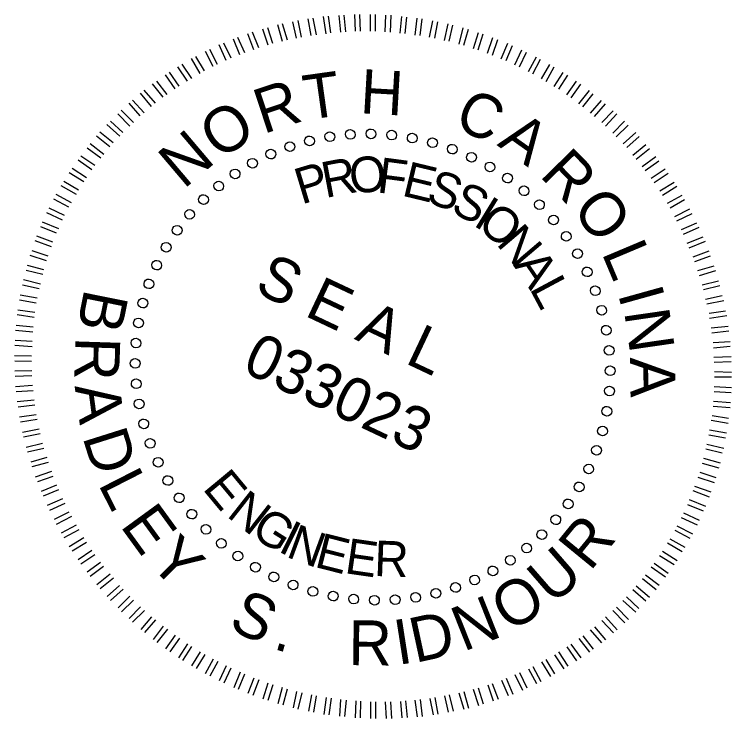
# Model space of a CAD drawing. Extents: x 1519210 to 1521378, y 637447 to 639183.
# Drawn here: x 1521293.4 to 1521377.9, y 638204.2 to 638287.1 of the extents above; entities that cross this region are included whole.
import ezdxf

# ---------------------------------------------------------------- set-up
doc = ezdxf.new("R2010")
doc.units = 0
doc.layers.add('Old_Level_2', color=7, linetype='Continuous')

msp = doc.modelspace()

# ---------------------------------------------------------------- linework, layer by layer
at = {"layer": 'Old_Level_2'}
for p, q in [((1521332.409, 638285.033), (1521332.203, 638287.004)), ((1521333.571, 638285.091), (1521333.479, 638287.063)), ((1521334.142, 638285.098), (1521334.05, 638287.069)), ((1521335.329, 638285.088), (1521335.305, 638287.083)), ((1521335.9, 638285.095), (1521335.922, 638287.067)), ((1521337.066, 638285.04), (1521337.135, 638286.991)), ((1521326.612, 638284.296), (1521326.157, 638286.219)), ((1521327.179, 638284.415), (1521326.791, 638286.361)), ((1521328.338, 638284.585), (1521327.971, 638286.575)), ((1521328.951, 638284.681), (1521328.563, 638286.627)), ((1521330.088, 638284.806), (1521329.789, 638286.82)), ((1521330.655, 638284.924), (1521330.381, 638286.871)), ((1521331.817, 638284.982), (1521331.611, 638286.952)), ((1521337.662, 638284.98), (1521337.752, 638286.976)), ((1521338.807, 638284.88), (1521338.99, 638286.833)), ((1521339.403, 638284.82), (1521339.586, 638286.772)), ((1521340.573, 638284.654), (1521340.824, 638286.629)), ((1521341.169, 638284.593), (1521341.419, 638286.568)), ((1521342.271, 638284.403), (1521342.661, 638286.313)), ((1521342.892, 638284.276), (1521343.236, 638286.207)), ((1521323.263, 638283.452), (1521322.626, 638285.35)), ((1521323.804, 638283.638), (1521323.213, 638285.514)), ((1521324.938, 638283.874), (1521324.389, 638285.841)), ((1521325.526, 638284.038), (1521324.956, 638285.959)), ((1521344.02, 638284.019), (1521344.478, 638285.952)), ((1521344.595, 638283.914), (1521345.031, 638285.801)), ((1521345.748, 638283.59), (1521346.251, 638285.501)), ((1521346.301, 638283.44), (1521346.851, 638285.329)), ((1521321.592, 638282.918), (1521320.887, 638284.793)), ((1521322.155, 638283.149), (1521321.429, 638284.978)), ((1521347.432, 638283.071), (1521348.029, 638284.938)), ((1521347.986, 638282.92), (1521348.582, 638284.788)), ((1521318.91, 638281.925), (1521318.048, 638283.708)), ((1521319.946, 638282.317), (1521319.174, 638284.169)), ((1521320.509, 638282.547), (1521319.715, 638284.354)), ((1521349.096, 638282.507), (1521349.739, 638284.352)), ((1521349.675, 638282.289), (1521350.318, 638284.134)), ((1521350.717, 638281.853), (1521351.475, 638283.699)), ((1521317.314, 638281.189), (1521316.385, 638282.95)), ((1521318.326, 638281.649), (1521317.485, 638283.478)), ((1521351.296, 638281.635), (1521352.032, 638283.436)), ((1521352.317, 638281.153), (1521353.146, 638282.911)), ((1521315.766, 638280.433), (1521314.747, 638282.125)), ((1521316.798, 638280.937), (1521315.869, 638282.698)), ((1521352.874, 638280.89), (1521353.703, 638282.648)), ((1521353.921, 638280.342), (1521354.864, 638282.1)), ((1521314.267, 638279.542), (1521313.135, 638281.233)), ((1521315.274, 638280.113), (1521314.231, 638281.872)), ((1521354.432, 638280.101), (1521355.354, 638281.814)), ((1521355.457, 638279.507), (1521356.425, 638281.199)), ((1521312.768, 638278.651), (1521311.661, 638280.275)), ((1521313.776, 638279.222), (1521312.644, 638280.913)), ((1521355.993, 638279.199), (1521356.961, 638280.891)), ((1521356.951, 638278.582), (1521358.012, 638280.23)), ((1521312.324, 638278.31), (1521311.17, 638279.956)), ((1521357.487, 638278.274), (1521358.548, 638279.922)), ((1521310.897, 638277.33), (1521309.654, 638278.908)), ((1521311.388, 638277.649), (1521310.145, 638279.227)), ((1521358.423, 638277.612), (1521359.577, 638279.217)), ((1521358.938, 638277.259), (1521360.092, 638278.864)), ((1521309.542, 638276.261), (1521308.231, 638277.816)), ((1521310.007, 638276.648), (1521308.676, 638278.157)), ((1521359.853, 638276.552), (1521361.1, 638278.113)), ((1521360.321, 638276.221), (1521361.547, 638277.737)), ((1521308.677, 638275.512), (1521307.278, 638276.998)), ((1521361.215, 638275.469), (1521362.534, 638276.941)), ((1521308.211, 638275.126), (1521306.88, 638276.635)), ((1521361.709, 638275.071), (1521362.981, 638276.565)), ((1521306.974, 638273.947), (1521305.554, 638275.388)), ((1521307.394, 638274.355), (1521305.973, 638275.796)), ((1521362.556, 638274.341), (1521363.9, 638275.746)), ((1521362.982, 638273.92), (1521364.347, 638275.37)), ((1521306.156, 638273.175), (1521304.693, 638274.526)), ((1521363.855, 638273.123), (1521365.245, 638274.505)), ((1521305.783, 638272.745), (1521304.274, 638274.118)), ((1521364.259, 638272.656), (1521365.649, 638274.039)), ((1521304.618, 638271.477), (1521303.066, 638272.76)), ((1521305.012, 638271.952), (1521303.46, 638273.235)), ((1521365.064, 638271.836), (1521366.547, 638273.175)), ((1521365.49, 638271.415), (1521366.951, 638272.709)), ((1521303.918, 638270.595), (1521302.298, 638271.855)), ((1521366.206, 638270.526), (1521367.76, 638271.776)), ((1521303.545, 638270.165), (1521301.95, 638271.358)), ((1521366.61, 638270.06), (1521368.165, 638271.31)), ((1521302.845, 638269.283), (1521301.208, 638270.386)), ((1521367.327, 638269.172), (1521368.906, 638270.355)), ((1521302.497, 638268.786), (1521300.881, 638269.934)), ((1521367.685, 638268.727), (1521369.289, 638269.843)), ((1521301.542, 638267.364), (1521299.838, 638268.443)), ((1521301.89, 638267.861), (1521300.186, 638268.94)), ((1521368.379, 638267.794), (1521370.031, 638268.888)), ((1521368.716, 638267.304), (1521370.367, 638268.398)), ((1521300.68, 638265.897), (1521298.887, 638266.908)), ((1521300.914, 638266.393), (1521299.188, 638267.427)), ((1521369.39, 638266.325), (1521371.066, 638267.353)), ((1521369.705, 638265.791), (1521371.403, 638266.863)), ((1521300.099, 638264.904), (1521298.284, 638265.87)), ((1521299.797, 638264.385), (1521298.029, 638265.33)), ((1521370.286, 638264.856), (1521372.034, 638265.794)), ((1521370.602, 638264.322), (1521372.303, 638265.282)), ((1521299.283, 638263.416), (1521297.472, 638264.27)), ((1521371.14, 638263.297), (1521372.934, 638264.213)), ((1521299.028, 638262.875), (1521297.217, 638263.729)), ((1521371.409, 638262.784), (1521373.182, 638263.655)), ((1521298.607, 638261.862), (1521296.707, 638262.648)), ((1521371.947, 638261.759), (1521373.745, 638262.563)), ((1521298.352, 638261.321), (1521296.499, 638262.085)), ((1521372.195, 638261.201), (1521374.015, 638262.051)), ((1521297.91, 638260.263), (1521296.035, 638260.981)), ((1521372.619, 638260.175), (1521374.489, 638260.891)), ((1521297.769, 638259.723), (1521295.826, 638260.419)), ((1521372.867, 638259.617), (1521374.758, 638260.378)), ((1521297.373, 638258.643), (1521295.456, 638259.272)), ((1521373.337, 638258.569), (1521375.186, 638259.24)), ((1521297.164, 638258.08), (1521295.247, 638258.709)), ((1521373.518, 638257.988), (1521375.366, 638258.659)), ((1521296.836, 638257.023), (1521294.923, 638257.54)), ((1521373.874, 638256.939), (1521375.773, 638257.476)), ((1521296.741, 638256.462), (1521294.76, 638256.955)), ((1521374.054, 638256.358), (1521375.974, 638256.94)), ((1521296.438, 638255.338), (1521294.457, 638255.831)), ((1521374.389, 638255.264), (1521376.313, 638255.733)), ((1521296.297, 638254.798), (1521294.342, 638255.225)), ((1521374.523, 638254.705), (1521376.447, 638255.174)), ((1521295.946, 638253.091), (1521293.969, 638253.472)), ((1521296.062, 638253.697), (1521294.064, 638254.033)), ((1521374.79, 638253.587), (1521376.74, 638253.99)), ((1521374.924, 638253.028), (1521376.92, 638253.409)), ((1521295.73, 638251.43), (1521293.711, 638251.721)), ((1521295.778, 638252.013), (1521293.805, 638252.282)), ((1521375.192, 638251.91), (1521377.145, 638252.201)), ((1521375.258, 638251.328), (1521377.279, 638251.642)), ((1521295.54, 638249.702), (1521293.524, 638249.881)), ((1521295.588, 638250.285), (1521293.572, 638250.464)), ((1521375.457, 638250.187), (1521377.436, 638250.411)), ((1521375.524, 638249.605), (1521377.502, 638249.829)), ((1521295.465, 638248.58), (1521293.474, 638248.692)), ((1521375.677, 638248.486), (1521377.659, 638248.598)), ((1521295.463, 638247.975), (1521293.426, 638248.109)), ((1521375.722, 638247.859), (1521377.679, 638248.038)), ((1521295.388, 638246.853), (1521293.377, 638246.92)), ((1521375.761, 638246.739), (1521377.79, 638246.829)), ((1521295.387, 638246.248), (1521293.421, 638246.293)), ((1521375.781, 638246.179), (1521377.788, 638246.224)), ((1521295.426, 638245.128), (1521293.418, 638245.083)), ((1521375.82, 638245.058), (1521377.831, 638244.991)), ((1521295.445, 638244.568), (1521293.463, 638244.456)), ((1521375.818, 638244.453), (1521377.851, 638244.431)), ((1521295.531, 638243.425), (1521293.527, 638243.269)), ((1521375.79, 638243.31), (1521377.826, 638243.176)), ((1521295.576, 638242.798), (1521293.593, 638242.687)), ((1521375.788, 638242.705), (1521377.778, 638242.592)), ((1521295.729, 638241.679), (1521293.704, 638241.477)), ((1521375.713, 638241.583), (1521377.729, 638241.404)), ((1521295.795, 638241.097), (1521293.817, 638240.873)), ((1521375.665, 638241), (1521377.681, 638240.82)), ((1521295.949, 638239.978), (1521293.995, 638239.688)), ((1521375.544, 638239.9), (1521377.495, 638239.586)), ((1521296.082, 638239.419), (1521294.108, 638239.084)), ((1521375.449, 638239.339), (1521377.447, 638239.002)), ((1521296.282, 638238.278), (1521294.333, 638237.876)), ((1521375.26, 638238.216), (1521377.237, 638237.834)), ((1521296.416, 638237.72), (1521294.466, 638237.317)), ((1521375.145, 638237.609), (1521377.143, 638237.273)), ((1521296.683, 638236.602), (1521294.759, 638236.132)), ((1521374.909, 638236.508), (1521376.911, 638236.06)), ((1521296.864, 638236.021), (1521294.939, 638235.551)), ((1521374.815, 638235.947), (1521376.749, 638235.475)), ((1521297.199, 638234.926), (1521295.3, 638234.39)), ((1521374.533, 638234.868), (1521376.492, 638234.329)), ((1521297.379, 638234.346), (1521295.433, 638233.831)), ((1521374.371, 638234.283), (1521376.33, 638233.745)), ((1521297.735, 638233.296), (1521295.84, 638232.648)), ((1521374.089, 638233.204), (1521376.006, 638232.576)), ((1521297.915, 638232.715), (1521296.088, 638232.09)), ((1521373.88, 638232.642), (1521375.797, 638232.013)), ((1521298.339, 638231.689), (1521296.516, 638230.952)), ((1521373.484, 638231.561), (1521375.38, 638230.888)), ((1521298.587, 638231.131), (1521296.764, 638230.394)), ((1521373.297, 638231.044), (1521375.218, 638230.303)), ((1521299.058, 638230.083), (1521297.259, 638229.279)), ((1521372.854, 638229.985), (1521374.754, 638229.2)), ((1521299.306, 638229.526), (1521297.507, 638228.721)), ((1521372.646, 638229.423), (1521374.499, 638228.659)), ((1521299.797, 638228.522), (1521298.071, 638227.629)), ((1521300.113, 638227.988), (1521298.319, 638227.071)), ((1521371.923, 638227.891), (1521373.78, 638227.015)), ((1521372.178, 638228.431), (1521374.035, 638227.555)), ((1521300.651, 638226.963), (1521298.903, 638226.025)), ((1521300.967, 638226.429), (1521299.219, 638225.49)), ((1521371.154, 638226.38), (1521372.922, 638225.436)), ((1521371.409, 638226.921), (1521373.224, 638225.955)), ((1521301.547, 638225.494), (1521299.85, 638224.421)), ((1521370.572, 638225.387), (1521372.319, 638224.398)), ((1521301.863, 638224.959), (1521300.187, 638223.932)), ((1521370.292, 638224.914), (1521372.018, 638223.879)), ((1521302.49, 638224.002), (1521300.885, 638222.886)), ((1521369.71, 638223.921), (1521371.415, 638222.842)), ((1521302.873, 638223.491), (1521301.222, 638222.397)), ((1521369.363, 638223.424), (1521371.067, 638222.345)), ((1521303.522, 638222.579), (1521301.963, 638221.441)), ((1521303.88, 638222.135), (1521302.3, 638220.952)), ((1521368.383, 638222.068), (1521370.045, 638220.899)), ((1521368.709, 638222.52), (1521370.371, 638221.351)), ((1521304.642, 638221.224), (1521303.088, 638219.974)), ((1521367.708, 638221.119), (1521369.302, 638219.927)), ((1521305.047, 638220.758), (1521303.492, 638219.508)), ((1521367.335, 638220.689), (1521368.954, 638219.43)), ((1521305.763, 638219.87), (1521304.301, 638218.576)), ((1521306.189, 638219.448), (1521304.706, 638218.11)), ((1521366.589, 638219.829), (1521368.187, 638218.525)), ((1521306.994, 638218.628), (1521305.604, 638217.245)), ((1521366.216, 638219.399), (1521367.746, 638218.071)), ((1521307.398, 638218.162), (1521306.008, 638216.779)), ((1521365.05, 638218.131), (1521366.559, 638216.758)), ((1521365.47, 638218.539), (1521366.932, 638217.188)), ((1521308.224, 638217.387), (1521306.881, 638215.982)), ((1521308.697, 638216.944), (1521307.307, 638215.561)), ((1521363.859, 638216.93), (1521365.28, 638215.489)), ((1521364.279, 638217.338), (1521365.699, 638215.897)), ((1521309.544, 638216.213), (1521308.272, 638214.72)), ((1521362.995, 638216.18), (1521364.373, 638214.649)), ((1521309.991, 638215.837), (1521308.719, 638214.344)), ((1521362.575, 638215.772), (1521363.928, 638214.308)), ((1521310.885, 638215.085), (1521309.706, 638213.548)), ((1521311.4, 638214.732), (1521310.153, 638213.172)), ((1521361.199, 638214.659), (1521362.53, 638213.149)), ((1521361.711, 638215.023), (1521362.975, 638213.491)), ((1521312.315, 638214.025), (1521311.161, 638212.421)), ((1521312.83, 638213.672), (1521311.676, 638212.068)), ((1521359.865, 638213.635), (1521361.107, 638212.058)), ((1521360.309, 638213.976), (1521361.552, 638212.399)), ((1521313.766, 638213.01), (1521312.705, 638211.362)), ((1521314.255, 638212.724), (1521313.194, 638211.076)), ((1521358.438, 638212.656), (1521359.591, 638211.01)), ((1521358.929, 638212.975), (1521360.104, 638211.374)), ((1521315.26, 638212.085), (1521314.245, 638210.415)), ((1521357.477, 638212.062), (1521358.563, 638210.393)), ((1521315.796, 638211.778), (1521314.781, 638210.108)), ((1521316.775, 638211.206), (1521315.853, 638209.492)), ((1521355.978, 638211.171), (1521356.997, 638209.479)), ((1521356.986, 638211.743), (1521358.072, 638210.074)), ((1521317.332, 638210.943), (1521316.41, 638209.229)), ((1521318.332, 638210.416), (1521317.503, 638208.659)), ((1521318.889, 638210.153), (1521318.06, 638208.396)), ((1521354.455, 638210.347), (1521355.384, 638208.587)), ((1521355.462, 638210.919), (1521356.505, 638209.16)), ((1521319.978, 638209.695), (1521319.221, 638207.848)), ((1521320.489, 638209.454), (1521319.753, 638207.653)), ((1521352.318, 638209.427), (1521353.205, 638207.576)), ((1521352.88, 638209.657), (1521353.721, 638207.829)), ((1521353.938, 638210.095), (1521354.868, 638208.335)), ((1521321.578, 638208.995), (1521320.889, 638207.172)), ((1521322.157, 638208.778), (1521321.467, 638206.954)), ((1521350.744, 638208.737), (1521351.538, 638206.93)), ((1521351.306, 638208.967), (1521352.079, 638207.116)), ((1521323.221, 638208.386), (1521322.624, 638206.519)), ((1521323.82, 638208.213), (1521323.224, 638206.346)), ((1521324.905, 638207.867), (1521324.402, 638205.956)), ((1521325.505, 638207.694), (1521325.001, 638205.783)), ((1521347.402, 638207.669), (1521348.039, 638205.771)), ((1521347.99, 638207.832), (1521348.581, 638205.956)), ((1521349.119, 638208.181), (1521349.778, 638206.328)), ((1521349.661, 638208.366), (1521350.366, 638206.491)), ((1521326.612, 638207.393), (1521326.222, 638205.483)), ((1521327.233, 638207.265), (1521326.775, 638205.332)), ((1521328.36, 638207.009), (1521328.017, 638205.077)), ((1521328.935, 638206.903), (1521328.592, 638204.972)), ((1521344.027, 638206.892), (1521344.483, 638204.969)), ((1521344.594, 638207.01), (1521345.049, 638205.087)), ((1521345.727, 638207.247), (1521346.297, 638205.325)), ((1521346.315, 638207.41), (1521346.863, 638205.444)), ((1521330.084, 638206.692), (1521329.833, 638204.716)), ((1521330.68, 638206.631), (1521330.429, 638204.656)), ((1521331.803, 638206.487), (1521331.667, 638204.513)), ((1521332.446, 638206.404), (1521332.263, 638204.452)), ((1521333.591, 638206.305), (1521333.501, 638204.309)), ((1521334.14, 638206.266), (1521334.118, 638204.293)), ((1521335.306, 638206.212), (1521335.331, 638204.217)), ((1521335.923, 638206.196), (1521335.901, 638204.224)), ((1521337.065, 638206.209), (1521337.156, 638204.237)), ((1521337.682, 638206.193), (1521337.773, 638204.222)), ((1521338.844, 638206.251), (1521339.004, 638204.303)), ((1521339.436, 638206.303), (1521339.642, 638204.332)), ((1521340.552, 638206.382), (1521340.825, 638204.435)), ((1521341.165, 638206.479), (1521341.417, 638204.487)), ((1521342.302, 638206.603), (1521342.69, 638204.658)), ((1521342.915, 638206.7), (1521343.235, 638204.731))]:
    msp.add_line(p, q, dxfattribs=at)
for centre in [(1521332.939, 638272.957), (1521335.376, 638273.023), (1521337.814, 638272.881), (1521328.144, 638272.2), (1521330.522, 638272.682), (1521340.236, 638272.531), (1521342.622, 638271.976), (1521325.822, 638271.517), (1521344.954, 638271.22), (1521323.574, 638270.636), (1521321.418, 638269.564), (1521347.215, 638270.269), (1521349.387, 638269.13), (1521319.37, 638268.309), (1521351.455, 638267.812), (1521317.445, 638266.882), (1521353.401, 638266.325), (1521315.658, 638265.293), (1521355.212, 638264.68), (1521314.022, 638263.553), (1521356.874, 638262.889), (1521312.551, 638261.677), (1521358.373, 638260.967), (1521311.255, 638259.678), (1521359.699, 638258.928), (1521310.144, 638257.572), (1521360.841, 638256.787), (1521309.226, 638255.375), (1521361.791, 638254.561), (1521308.509, 638253.104), (1521362.542, 638252.266), (1521307.999, 638250.775), (1521363.087, 638249.921), (1521307.698, 638248.406), (1521363.423, 638247.542), (1521307.609, 638246.016), (1521363.547, 638245.149), (1521307.733, 638243.623), (1521363.459, 638242.759), (1521308.069, 638241.245), (1521363.158, 638240.391), (1521308.614, 638238.899), (1521362.647, 638238.062), (1521309.365, 638236.605), (1521361.93, 638235.79), (1521310.315, 638234.379), (1521361.013, 638233.593), (1521311.457, 638232.238), (1521359.902, 638231.487), (1521312.783, 638230.198), (1521358.605, 638229.488), (1521314.282, 638228.276), (1521357.134, 638227.612), (1521315.944, 638226.486), (1521355.499, 638225.873), (1521317.755, 638224.841), (1521353.712, 638224.283), (1521319.701, 638223.353), (1521351.787, 638222.856), (1521321.769, 638222.035), (1521349.738, 638221.602), (1521323.941, 638220.896), (1521347.582, 638220.53), (1521326.202, 638219.945), (1521345.334, 638219.649), (1521328.535, 638219.189), (1521343.013, 638218.965), (1521330.921, 638218.634), (1521333.342, 638218.284), (1521335.781, 638218.142), (1521338.218, 638218.209), (1521340.634, 638218.484)]:
    msp.add_ellipse(centre, major_axis=(0.526, -0.248), ratio=0.970588, dxfattribs=at)

# ---------------------------------------------------------------- texts
for s, height, rotation, p in [('T', 5.248, 7.95241, (1521327.795, 638274.649)), ('H', 5.205, 356.76499, (1521334.023, 638275.458)), ('R', 5.283, 18.30762, (1521322.694, 638272.978)), ('C', 5.159, 335.54521, (1521344.969, 638273.876)), ('O', 5.312, 32.93215, (1521317.483, 638269.872)), ('A', 5.17, 324.74938, (1521350.136, 638271.715)), ('N', 5.317, 40.32106, (1521313.31, 638266.441)), ('R', 5.2, 314.33822, (1521355.126, 638268.094)), ('R', 4.218, 10.70401, (1521329.989, 638265.461)), ('O', 4.2, 4.59292, (1521332.962, 638265.987)), ('F', 4.164, 352.46702, (1521335.992, 638266.156)), ('P', 4.235, 16.85251, (1521327.185, 638264.69)), ('E', 4.151, 346.44092, (1521338.882, 638265.784)), ('S', 4.142, 340.43015, (1521341.716, 638265.054)), ('S', 4.139, 334.42699, (1521344.612, 638263.853)), ('O', 5.226, 307.21442, (1521358.94, 638264.147)), ('I', 4.142, 328.42338, (1521347.292, 638262.314)), ('O', 4.151, 322.41133, (1521347.714, 638262.005)), ('N', 4.183, 310.33173, (1521350.041, 638260.081)), ('L', 5.278, 292.82783, (1521362.498, 638259.054)), ('S E A L', 5.1785, 334.75051, (1521321.495, 638254.483)), ('A', 4.201, 304.251, (1521352.093, 638257.571)), ('L', 4.22, 298.13602, (1521353.992, 638254.857)), ('I', 5.297, 285.5549, (1521364.425, 638254.234)), ('B', 5.283, 258.64176, (1521301.66, 638254.921)), ('N', 5.31, 278.22758, (1521365.184, 638252.113)), ('033023', 5.1785, 334.75051, (1521320.022, 638245.155)), ('R', 5.283, 268.15709, (1521300.583, 638249.185)), ('A', 5.316, 270.84932, (1521365.875, 638246.719)), ('A', 5.283, 277.67243, (1521300.469, 638243.351)), ('D', 5.283, 287.50495, (1521301.366, 638237.388)), ('L', 5.283, 297.02028, (1521303.191, 638231.845)), ('E', 4.185, 309.6777, (1521315.455, 638231.274)), ('N', 4.153, 321.76236, (1521318.261, 638228.078)), ('E', 5.283, 306.05985, (1521305.752, 638226.927)), ('G', 4.143, 327.7758, (1521321.057, 638225.823)), ('I', 4.138, 333.77993, (1521324.319, 638223.954)), ('N', 4.14, 339.78275, (1521325.256, 638223.292)), ('R', 5.283, 50.72857, (1521361.179, 638221.453)), ('Y', 5.283, 315.09943, (1521309.054, 638222.473)), ('E', 4.149, 345.79232, (1521328.608, 638222.096)), ('E', 4.163, 351.81642, (1521332.173, 638221.351)), ('R', 4.179, 357.86226, (1521335.701, 638221.01)), ('U', 5.283, 41.05464, (1521356.76, 638217.494)), ('O', 5.283, 31.22213, (1521351.652, 638214.29)), ('S', 5.283, 334.84375, (1521318.42, 638214.871)), ('N', 5.283, 21.70679, (1521346.258, 638212.063)), ('D', 5.283, 12.19145, (1521340.569, 638210.759)), ('R', 5.283, 359.34575, (1521332.702, 638210.52)), ('I', 5.283, 8.86108, (1521338.538, 638210.527)), ('.', 5.283, 344.35909, (1521323.733, 638212.457))]:
    msp.add_text(s, height=height, rotation=rotation, dxfattribs=at).set_placement(p)

doc.saveas('drawing.dxf')
